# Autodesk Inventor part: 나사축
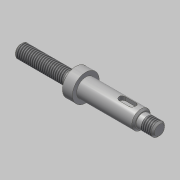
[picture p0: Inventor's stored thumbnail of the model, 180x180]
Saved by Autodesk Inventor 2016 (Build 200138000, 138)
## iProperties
Created: 2019-10
Part Number: 나사축
Material: 강철, 연강
Document SubType Name: Modeling
Designer: mduedu
Density: 1 g/cm^3
Appearance: 강철
Author: mduedu
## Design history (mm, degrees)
sketch "스케치1"
  geometry: L1 (0, 0)-(33, 0); L2 (33, 0)-(33, 4); L3 (33, 4)-(0, 4); L4 (0, 4)-(0, 0); L5 (33, 0)-(39, 0); L6 (39, 0)-(39, 8); L7 (39, 8)-(33, 8); L8 (33, 8)-(33, 0); L9 (39, 0)-(73, 0); L10 (73, 0)-(73, 5.5); L11 (73, 5.5)-(39, 5.5); L12 (39, 5.5)-(39, 0); L13 (73, 0)-(83, 0); L14 (83, 0)-(83, 4); L15 (83, 4)-(73, 4); L16 (73, 4)-(73, 0)
  constraints: 32 end point, 8 parallel, 4 horizontal, 4 perpendicular
  dimensions: "d0" = 83 distance between parallel lines of L14 L4; "d2" = 8 diameter of L15 L13; "d3" = 11 diameter of L11 L9; "d4" = 16 diameter of L7 L5; "d5" = 8 diameter of L3 L1; "d6" = 33 distance of L2.end L3.end; "d7" = 6 distance of L6.end L7.end; "d8" = 40 distance between parallel lines of L10 L8
revolve "회전1" sketch "스케치1" stored, may be unused: angle "d9" = 90 deg
sketch "스케치2"
  geometry: L1 (0, 4)-(0, -4) reference; L2 (0, -4)-(-33, -4) reference; L3 (-33, -4)-(-33, -8) reference; L4 (-33, -8)-(-39, -8) reference; L5 (-39, -8)-(-39, -5.5) reference; L6 (-39, -5.5)-(-73, -5.5) reference; L7 (-73, -5.5)-(-73, -4) reference; L8 (-73, -4)-(-83, -4) reference; L9 (-83, -4)-(-83, 4) reference; L10 (-83, 4)-(-73, 4) reference; L11 (-73, 4)-(-73, 5.5) reference; L12 (-73, 5.5)-(-39, 5.5) reference; L13 (-39, 5.5)-(-39, 8) reference; L14 (-39, 8)-(-33, 8) reference; L15 (-33, 8)-(-33, 4) reference; L16 (-33, 4)-(0, 4) reference; L17 (0, 0)-(-83, 0); L18 (-31, 3)-(-33, 3); L19 (-33, 3)-(-33, 4); L20 (-31, 3)-(-29.268, 4); L21 (-33, 4)-(-29.268, 4)
  constraints: 10 end point, 1 collinear, 1 midpoint, 1 point on line, 1 vertical
  dimensions: "d13" = 1 distance between parallel lines of L18 L21; "d15" = 30 deg angle of L16 L20; "d17" = 2 distance of L18.start L18.end
revolve "회전2" sketch "스케치2" stored, may be unused: angle "d12" = 90 deg
feature "스레드1" dims "d18" = 10, "d19" = 0
feature "스레드2" dims "d20" = 7, "d21" = 0
chamfer "모따기1" distance "d22" = 1; stored, may be unused: second distance "d23" = 2, angle "d24" = 30 deg
chamfer "모따기2" distance "d25" = 1; stored, may be unused: second distance "d26" = 2, angle "d27" = 30 deg
sketch "스케치3"
  geometry: L1 (-31, -3)-(-33, -3) reference; L2 (-33, -3)-(-33, -8) reference; L3 (-33, -8)-(-39, -8) reference; L4 (-39, -8)-(-39, -5.5) reference; L5 (-39, -5.5)-(-72, -5.5) reference; L6 (-72, -5.5)-(-73, -4.5) reference; L7 (-73, -4.5)-(-73, -4) reference; L8 (-73, -4)-(-82, -4) reference; L9 (-82, -4)-(-83, -3) reference; L10 (-83, -3)-(-83, 3) reference; L11 (-83, 3)-(-82, 4) reference; L12 (-82, 4)-(-73, 4) reference; L13 (-73, 4)-(-73, 4.5) reference; L14 (-73, 4.5)-(-72, 5.5) reference; L15 (-72, 5.5)-(-39, 5.5) reference; L16 (-39, 5.5)-(-39, 8) reference; L17 (-39, 8)-(-33, 8) reference; L18 (-33, 8)-(-33, 3) reference; L19 (-33, 3)-(-31, 3) reference; L20 (-31, 3)-(-29.268, 4) reference; L21 (-29.268, 4)-(-1, 4) reference; L22 (-1, 4)-(0, 3) reference; L23 (0, 3)-(0, -3) reference; L24 (0, -3)-(-1, -4) reference; L25 (-1, -4)-(-29.268, -4) reference; L26 (-29.268, -4)-(-31, -3) reference; L27 (-59, 5.5)-(-69, 5.5); L28 (-69, 5.5)-(-69, 3); L29 (-69, 3)-(-59, 3); L30 (-59, 3)-(-59, 5.5); 1 further point
  constraints: 8 end point, 2 parallel, 1 horizontal, 1 perpendicular, 1 point on line
  dimensions: "d28" = 20 distance between parallel lines of L30 L16; "d29" = 10 distance of L27.start L27.end; "d30" = 2.5 distance of L27.end L28.end
extrude "돌출1" cut sketch "스케치3" stored distance "d31" = 4; taper "d32" = 0 deg
fillet "모깎기1"
fillet "모깎기2"
node "솔리드1"
node "절단 모서리 투영1"
node "절단 모서리 투영2"
